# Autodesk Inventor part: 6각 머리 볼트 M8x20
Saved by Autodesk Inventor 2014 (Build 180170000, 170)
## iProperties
Created: 2026-04
Part Number: 6각 머리 볼트 M8x20
Material: 강철, 연강
Document SubType Name: Modeling
Designer: dg
Density: 7.86 g/cm^3
Appearance: 강철
Author: jhkim
Description: 6각 머리 볼트 및 6각 머리 나사
Creation Date: 2026-03-27
Sending System: Autodesk Inventor 2026
Preprocessor: ST-DEVELOPER v20.1
Author: dg
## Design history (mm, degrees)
node "6각 머리 볼트 M8x201"
body "Solid1"
node "기준1"
